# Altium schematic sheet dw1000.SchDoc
size A
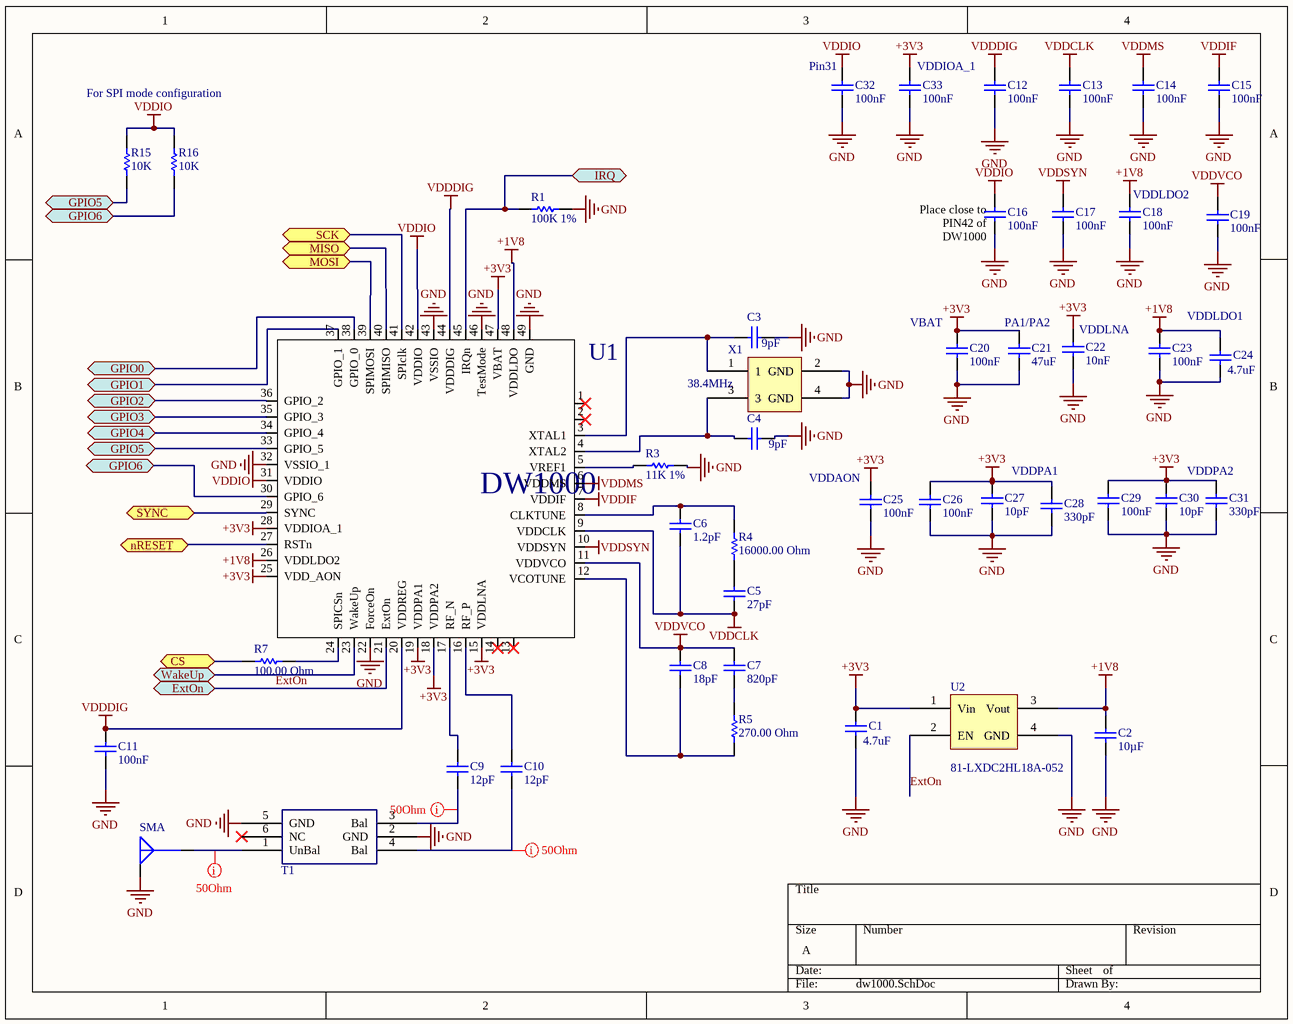
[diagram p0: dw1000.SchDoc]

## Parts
C1  4.7uF  [CAPC0603(1608)100_M]
C2  10µF  [CAPC1608X100X35ML20T25]
C3  9pF  [CAPC0402(1005)60_L]
C4  9pF  [CAPC0402(1005)60_L]
C5  27pF  [CAPC0402(1005)60_L]
C6  1.2pF  [CAPC0402(1005)60_L]
C7  820pF  [CAPC0402(1005)60_L]
C8  18pF  [CAPC0402(1005)60_L]
C9  12pF  [CAPC0402(1005)60_L]
C10  12pF  [CAPC0402(1005)60_L]
C11  100nF  [CAPC0402(1005)60_L]
C12  100nF  [CAPC0402(1005)60_L]
C13  100nF  [CAPC0402(1005)60_L]
C14  100nF  [CAPC0402(1005)60_L]
C15  100nF  [CAPC0402(1005)60_L]
C16  100nF  [CAPC0402(1005)60_L]
C17  100nF  [CAPC0402(1005)60_L]
C18  100nF  [CAPC0402(1005)60_L]
C19  100nF  [CAPC0402(1005)60_L]
C20  100nF  [CAPC0402(1005)60_L]
C21  47uF  [CAPC0805(2012)145_L]
C22  10nF  [CAPC0402(1005)60_L]
C23  100nF  [CAPC0402(1005)60_L]
C24  4.7uF  [CAPC0603(1608)100_M]
C25  100nF  [CAPC0402(1005)60_L]
C26  100nF  [CAPC0402(1005)60_L]
C27  10pF  [CAPC0402(1005)60_L]
C28  330pF  [CAPC0402(1005)60_L]
C29  100nF  [CAPC0402(1005)60_L]
C30  10pF  [CAPC0402(1005)60_L]
C31  330pF  [CAPC0402(1005)60_L]
C32  100nF  [CAPC0402(1005)60_L]
C33  100nF  [CAPC0402(1005)60_L]
R1  100K 1%  [RESC0402(1005)_M]
R3  11K 1%  [RESC0402(1005)_L]
R4  16000.00 Ohm  [RESC0402(1005)_L]
R5  270.00 Ohm  [RESC0402(1005)_L]
R7  100.00 Ohm  [RESC0402(1005)_L]
R15  10K  [RESC0603(1608)_L]
R16  10K  [RESC0603(1608)_L]
SMA  0732511150  [sma_footprint]  (value not drawn)
T1  HHM1595A1  [HHM1595A1]  (value not drawn)
U1  DW1000 IC  [QFN-48]  (value not drawn)
U2  81-LXDC2HL18A-052  [PCBComponent_1]
X1  38.4MHz  [tsx_3225fp]

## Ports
CS (bidir), ExtOn (bidir), GPIO0 (bidir), GPIO1 (bidir), GPIO2 (bidir), GPIO3 (bidir), GPIO4 (bidir), GPIO5 (bidir), GPIO6 (bidir), IRQ (bidir), MISO (bidir), MOSI (bidir), nRESET (bidir), SCK (bidir), SYNC (bidir), WakeUp (bidir)

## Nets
+1V8: C2.1 C18.1 C23.1 C24.2 U1.26(VDDLDO2) U1.48(VDDLDO) U2.3(Vout)
+3V3: C1.2 C20.1 C21.2 C22.1 C25.1 C26.1 C27.2 C28.1 C29.1 C30.2 C31.1 C33.1 U1.15(VDDLNA) U1.18(VDDPA2) U1.19(VDDPA1) U1.25(VDD_AON) U1.28(VDDIOA_1) U1.47(VBAT) U2.1(Vin)
GND: C1.1 C2.2 C3.2 C4.2 C11.2 C12.2 C13.2 C14.2 C15.2 C16.2 C17.2 C18.2 C19.2 C20.2 C21.1 C22.2 C23.2 C24.1 C25.2 C26.2 C27.1 C28.2 C29.2 C30.1 C31.2 C32.2 C33.2 R1.2 R3.2 SMA.G T1.2(GND) T1.5(GND) U1.22(ForceOn) U1.32(VSSIO_1) U1.43(VSSIO) U1.46(TestMode) U1.49(GND) U2.4(GND) X1.2(GND) X1.4(GND)
VDDCLK: C5.2 C6.2 C13.1 U1.9(VDDCLK)
VDDDIG: C11.1 C12.1 U1.20(VDDREG) U1.44(VDDDIG)
VDDIF: C15.1 U1.7(VDDIF)
VDDIO: C16.1 C32.1 R15.2 R16.2 U1.31(VDDIO) U1.42(VDDIO)
VDDMS: C14.1 U1.6(VDDMS)
VDDSYN: C17.1 U1.10(VDDSYN)
VDDVCO: C7.1 C8.2 C19.1 U1.11(VDDVCO)
CS: R7.2 ; port CS
ExtOn: U1.21(ExtOn) U2.2(EN) ; port ExtOn
GPIO0: U1.38(GPIO_0) ; port GPIO0
GPIO1: U1.37(GPIO_1) ; port GPIO1
GPIO2: U1.36(GPIO_2) ; port GPIO2
GPIO3: U1.35(GPIO_3) ; port GPIO3
GPIO4: U1.34(GPIO_4) ; port GPIO4
GPIO5: R15.1 U1.33(GPIO_5) ; port GPIO5
GPIO6: R16.1 U1.30(GPIO_6) ; port GPIO6
IRQ: R1.1 U1.45(IRQn) ; port IRQ
MISO: U1.40(SPIMISO) ; port MISO
MOSI: U1.39(SPIMOSI) ; port MOSI
nRESET: U1.27(RSTn) ; port nRESET
SCK: U1.41(SPIclk) ; port SCK
SYNC: U1.29(SYNC) ; port SYNC
WakeUp: U1.23(WakeUp) ; port WakeUp
NetC3_1: C3.1 U1.3(XTAL1) X1.1
NetC4_1: C4.1 U1.4(XTAL2) X1.3
NetC5_1: C5.1 R4.2
NetC6_1: C6.1 R4.1 U1.8(CLKTUNE)
NetC7_2: C7.2 R5.1
NetC8_1: C8.1 R5.2 U1.12(VCOTUNE)
NetC9_1: C9.1 U1.17(RF_N)
NetC9_2: C9.2 T1.3(Bal)
NetC10_1: C10.1 U1.16(RF_P)
NetC10_2: C10.2 T1.4(Bal)
NetR3_1: R3.1 U1.5(VREF1)
NetR7_1: R7.1 U1.24(SPICSn)
NetSMA_S: SMA.S T1.1(UnBal)

Not connected (* = marked no-connect by the designer): T1 6(NC)*; U1 1* 2* 13* 14*

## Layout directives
rule Impedance Constraint [Min = 50.00    Max = 50.00    ]: NetC9_2, NetC10_2, NetSMA_S

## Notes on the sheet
- For SPI mode configuration
- (near C32) Pin31
- (near C33) VDDIOA_1
- (near C18) VDDLDO2
- (near C16) Place close to PIN42 of DW1000
- (near C20) VBAT
- (near C21) PA1/PA2
- (near C22) VDDLNA
- VDDLDO1
- (near C25) VDDAON
- VDDPA1
- VDDPA2

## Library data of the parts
C1 C24 = CMP-1035-02780-1: CAP 4.7uF 6.3V ±10% 0603 (1608 Metric) Thickness 1mm SMD; Case-Metric: 1608; Case-EIA: 0603; Tolerance: Â±10%
C2 = CMP-2000-05443-1: High Value Multilayer Ceramic Capacitor, 10 uF, +/- 20%, 10 V, -55 to 85 degC, 0603 (1608 Metric), RoHS, Tape and Reel; Manufacturer: Taiyo Yuden; Voltage - Rated: 10V; Catalog Drawings: xMKSeries_0603_0.8; Temperature Coefficient: X5R; Other Names: 587-2562-6; Featured Product: MultilayerChipCapacitors; Online Catalog: MSeries
C3 C4 = CMP-1034-00643-1: CAP 9pF 50V ±0.05pF 0402 (1005 Metric) Thickness 0.6mm SMD; Case-Metric: 1005; Case-EIA: 0402; Tolerance: Â±0.05pF
C5 = CMP-1034-00961-1: CAP 27pF 50V ±2% 0402 (1005 Metric) Thickness 0.6mm SMD; Tolerance: Â±2%; Case-EIA: 0402; Case-Metric: 1005
C6 = CMP-1034-00083-1: CAP 1.2pF 50V ±0.05pF 0402 (1005 Metric) Thickness 0.6mm SMD; Case-EIA: 0402; Tolerance: Â±0.05pF; Case-Metric: 1005
C7 = CMP-1034-01592-1: CAP 820pF 50V ±2% 0402 (1005 Metric) Thickness 0.6mm SMD; Case-Metric: 1005; Tolerance: Â±2%; Case-EIA: 0402
C8 = CMP-1034-00863-1: CAP 18pF 50V ±2% 0402 (1005 Metric) Thickness 0.6mm SMD; Case-Metric: 1005; Case-EIA: 0402; Tolerance: Â±2%
C9 C10 = CMP-1034-00768-1: CAP 12pF 50V ±2% 0402 (1005 Metric) Thickness 0.6mm SMD; Case-EIA: 0402; Case-Metric: 1005; Tolerance: Â±2%
C11-C20 C23 C25 C26 C29 C32 C33 = CMP-1034-02069-1: CAP 100nF 16V ±10% 0402 (1005 Metric) Thickness 0.6mm SMD; Case-EIA: 0402; Case-Metric: 1005; Tolerance: Â±10%
C21 = CMP-1036-04950-1: CAP 47uF 6.3V ±20% 0805 (2012 Metric) Thickness 1.45mm SMD; Case-EIA: 0805; Case-Metric: 2012; Tolerance: Â±20%
C22 = CMP-1034-01880-1: CAP 10nF 25V ±10% 0402 (1005 Metric) Thickness 0.6mm SMD; Tolerance: Â±10%; Case-Metric: 1005; Case-EIA: 0402
C27 C30 = CMP-1034-00722-1: CAP 10pF 50V ±2% 0402 (1005 Metric) Thickness 0.6mm SMD; Tolerance: Â±2%; Case-Metric: 1005; Case-EIA: 0402
C28 C31 = CMP-1034-01432-1: CAP 330pF 50V ±2% 0402 (1005 Metric) Thickness 0.6mm SMD; Tolerance: Â±2%; Case-EIA: 0402; Case-Metric: 1005
R1 = CMP-1011-00736-1: 100K 0.063W 1% 0402 (1005 Metric)  SMD; Value: 100000.00 Ohm; Case-EIA: 0402; Case-Metric: 1005
R3 = CMP-1011-00627-1: 11K 0.063W 1% 0402 (1005 Metric)  SMD; Case-EIA: 0402; Case-Metric: 1005; Value: 11000.00 Ohm
R4 = CMP-1011-00644-1: 16K 0.063W 1% 0402 (1005 Metric)  SMD; Case-EIA: 0402; Case-Metric: 1005
R5 = CMP-1011-00444-1: 270R 0.063W 1% 0402 (1005 Metric)  SMD; Case-EIA: 0402; Case-Metric: 1005
R7 = CMP-1011-00397-1: 100R 0.063W 1% 0402 (1005 Metric)  SMD; Case-EIA: 0402; Case-Metric: 1005
R15 R16 = CMP-1012-00098-1: 10K 0.1W 5% 0603 (1608 Metric)  SMD; Case-EIA: 0603; Value: 10000.00 Ohm; Case-Metric: 1608
SMA = 0732511150: CONN SMA JACK 50 OHM EDGE MNT; Manufacturer: Molex, LLC; Contact Termination: Solder; Impedance: 50 Ohm; Frequency - Max: 18GHz; Body Material: Brass; Body Finish: Gold; Center Contact Material: Beryllium Copper; Dielectric Material: Polytetrafluoroethylene (PTFE); Voltage Rating: 500V
T1 = HHM1595A1: HHM1595A1 3000MHz - 8000MHz 0805; Category Letter: T
U1 = DW1000_QFN_48: UWB DW1000; Manufacturer: Decawave Ltd.
U2 X1 = Component_1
